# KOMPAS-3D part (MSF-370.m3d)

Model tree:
1. Ось X
2. Ось Y
3. Ось Z
4. Начало координат  (labels: Операция без истории:1)

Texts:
  Линия-выноска #1
  Линия-выноска #2
  Линия-выноска #3
  Отклонения формы и база
  Марка координационной оси
  Марка/позиционное обозначение с линией-выноской
  Марка/позиционное обозначение на линии
  Марка/позиционное обозначение без линии-выноски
